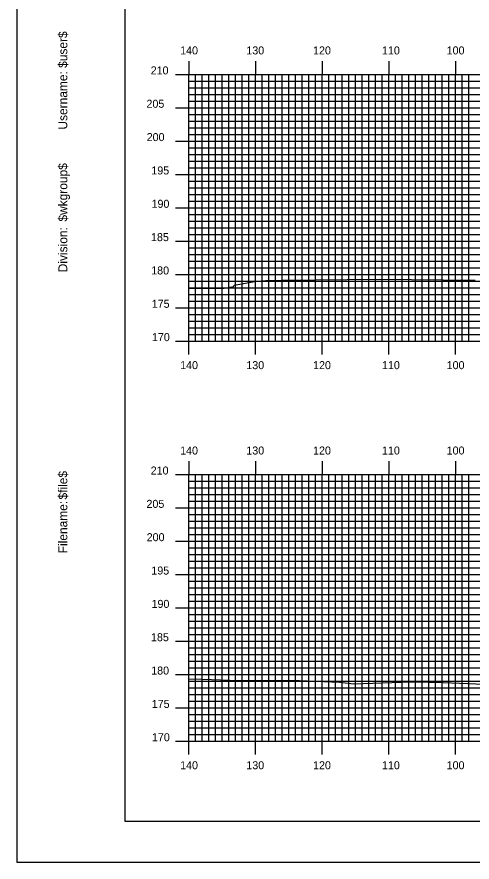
# Model space of a CAD drawing. Extents: x 1809406 to 1809749, y 442591 to 442811.
# Drawn here: x 1809406.1 to 1809474.3, y 442590.5 to 442717.3 of the extents above; entities that cross this region are included whole.
import ezdxf

# ---------------------------------------------------------------- set-up
doc = ezdxf.new("R2010")
doc.units = 0
for name, color, linetype in [('BORDER', 7, 'Continuous'), ('H_V ANNOTATION', 7, 'Continuous'), ('MAJOR', 7, 'Continuous'), ('MINOR', 7, 'Continuous'), ('PLOT BOUNDARY', 7, 'Continuous'), ('S_Roadway_Centerline', 7, 'Continuous')]:
    doc.layers.add(name, color=color, linetype=linetype)

msp = doc.modelspace()

# ---------------------------------------------------------------- linework, layer by layer
at = {"layer": 'BORDER'}
msp.add_lwpolyline([(1809422.24, 442596.67), (1809742.24, 442596.67), (1809742.24, 442806.67), (1809422.24, 442806.67)], close=True, dxfattribs=at)
at = {"layer": 'MAJOR'}
for p, q in [((1809431.84, 442710.67), (1809431.84, 442708.67)), ((1809441.84, 442710.67), (1809441.84, 442708.67)), ((1809451.84, 442710.67), (1809451.84, 442708.67)), ((1809461.84, 442710.67), (1809461.84, 442708.67)), ((1809471.84, 442710.67), (1809471.84, 442708.67)), ((1809429.83, 442708.67), (1809431.84, 442708.67)), ((1809431.84, 442708.67), (1809711.84, 442708.67)), ((1809431.84, 442668.67), (1809431.84, 442708.67)), ((1809431.84, 442668.67), (1809431.84, 442708.67)), ((1809431.84, 442708.67), (1809711.84, 442708.67)), ((1809441.84, 442668.67), (1809441.84, 442708.67)), ((1809451.84, 442668.67), (1809451.84, 442708.67)), ((1809461.84, 442668.67), (1809461.84, 442708.67)), ((1809471.84, 442668.67), (1809471.84, 442708.67)), ((1809429.83, 442703.67), (1809431.84, 442703.67)), ((1809431.84, 442703.67), (1809711.84, 442703.67)), ((1809429.83, 442698.67), (1809431.84, 442698.67)), ((1809431.84, 442698.67), (1809711.84, 442698.67)), ((1809429.83, 442693.67), (1809431.84, 442693.67)), ((1809431.84, 442693.67), (1809711.84, 442693.67)), ((1809429.83, 442688.67), (1809431.84, 442688.67)), ((1809431.84, 442688.67), (1809711.84, 442688.67)), ((1809429.83, 442683.67), (1809431.84, 442683.67)), ((1809431.84, 442683.67), (1809711.84, 442683.67)), ((1809429.83, 442678.67), (1809431.84, 442678.67)), ((1809431.84, 442678.67), (1809711.84, 442678.67)), ((1809429.83, 442673.67), (1809431.84, 442673.67)), ((1809431.84, 442673.67), (1809711.84, 442673.67)), ((1809429.83, 442668.67), (1809431.84, 442668.67)), ((1809431.84, 442668.67), (1809711.84, 442668.67)), ((1809431.84, 442668.67), (1809711.84, 442668.67)), ((1809431.84, 442666.66), (1809431.84, 442668.67)), ((1809441.84, 442666.66), (1809441.84, 442668.67)), ((1809451.84, 442666.66), (1809451.84, 442668.67)), ((1809461.84, 442666.66), (1809461.84, 442668.67)), ((1809471.84, 442666.66), (1809471.84, 442668.67)), ((1809431.84, 442650.67), (1809431.84, 442648.67)), ((1809441.84, 442650.67), (1809441.84, 442648.67)), ((1809451.84, 442650.67), (1809451.84, 442648.67)), ((1809461.84, 442650.67), (1809461.84, 442648.67)), ((1809471.84, 442650.67), (1809471.84, 442648.67)), ((1809429.83, 442648.67), (1809431.84, 442648.67)), ((1809431.84, 442648.67), (1809711.84, 442648.67)), ((1809431.84, 442608.67), (1809431.84, 442648.67)), ((1809431.84, 442608.67), (1809431.84, 442648.67)), ((1809431.84, 442648.67), (1809711.84, 442648.67)), ((1809441.84, 442608.67), (1809441.84, 442648.67)), ((1809451.84, 442608.67), (1809451.84, 442648.67)), ((1809461.84, 442608.67), (1809461.84, 442648.67)), ((1809471.84, 442608.67), (1809471.84, 442648.67)), ((1809429.83, 442643.67), (1809431.84, 442643.67)), ((1809431.84, 442643.67), (1809711.84, 442643.67)), ((1809429.83, 442638.67), (1809431.84, 442638.67)), ((1809431.84, 442638.67), (1809711.84, 442638.67)), ((1809429.83, 442633.67), (1809431.84, 442633.67)), ((1809431.84, 442633.67), (1809711.84, 442633.67)), ((1809429.83, 442628.67), (1809431.84, 442628.67)), ((1809431.84, 442628.67), (1809711.84, 442628.67)), ((1809429.83, 442623.67), (1809431.84, 442623.67)), ((1809431.84, 442623.67), (1809711.84, 442623.67)), ((1809429.83, 442618.67), (1809431.84, 442618.67)), ((1809431.84, 442618.67), (1809711.84, 442618.67)), ((1809429.83, 442613.67), (1809431.84, 442613.67)), ((1809431.84, 442613.67), (1809711.84, 442613.67)), ((1809429.83, 442608.67), (1809431.84, 442608.67)), ((1809431.84, 442608.67), (1809711.84, 442608.67)), ((1809431.84, 442608.67), (1809711.84, 442608.67)), ((1809431.84, 442606.66), (1809431.84, 442608.67)), ((1809441.84, 442606.66), (1809441.84, 442608.67)), ((1809451.84, 442606.66), (1809451.84, 442608.67)), ((1809461.84, 442606.66), (1809461.84, 442608.67)), ((1809471.84, 442606.66), (1809471.84, 442608.67))]:
    msp.add_line(p, q, dxfattribs=at)
at = {"layer": 'MINOR'}
for p, q in [((1809432.84, 442668.67), (1809432.84, 442708.67)), ((1809433.84, 442668.67), (1809433.84, 442708.67)), ((1809434.84, 442668.67), (1809434.84, 442708.67)), ((1809435.84, 442668.67), (1809435.84, 442708.67)), ((1809436.84, 442668.67), (1809436.84, 442708.67)), ((1809437.84, 442668.67), (1809437.84, 442708.67)), ((1809438.84, 442668.67), (1809438.84, 442708.67)), ((1809439.84, 442668.67), (1809439.84, 442708.67)), ((1809440.84, 442668.67), (1809440.84, 442708.67)), ((1809442.84, 442668.67), (1809442.84, 442708.67)), ((1809443.84, 442668.67), (1809443.84, 442708.67)), ((1809444.84, 442668.67), (1809444.84, 442708.67)), ((1809445.84, 442668.67), (1809445.84, 442708.67)), ((1809446.84, 442668.67), (1809446.84, 442708.67)), ((1809447.84, 442668.67), (1809447.84, 442708.67)), ((1809448.84, 442668.67), (1809448.84, 442708.67)), ((1809449.84, 442668.67), (1809449.84, 442708.67)), ((1809450.84, 442668.67), (1809450.84, 442708.67)), ((1809452.84, 442668.67), (1809452.84, 442708.67)), ((1809453.84, 442668.67), (1809453.84, 442708.67)), ((1809454.84, 442668.67), (1809454.84, 442708.67)), ((1809455.84, 442668.67), (1809455.84, 442708.67)), ((1809456.84, 442668.67), (1809456.84, 442708.67)), ((1809457.84, 442668.67), (1809457.84, 442708.67)), ((1809458.84, 442668.67), (1809458.84, 442708.67)), ((1809459.84, 442668.67), (1809459.84, 442708.67)), ((1809460.84, 442668.67), (1809460.84, 442708.67)), ((1809462.84, 442668.67), (1809462.84, 442708.67)), ((1809463.84, 442668.67), (1809463.84, 442708.67)), ((1809464.84, 442668.67), (1809464.84, 442708.67)), ((1809465.84, 442668.67), (1809465.84, 442708.67)), ((1809466.84, 442668.67), (1809466.84, 442708.67)), ((1809467.84, 442668.67), (1809467.84, 442708.67)), ((1809468.84, 442668.67), (1809468.84, 442708.67)), ((1809469.84, 442668.67), (1809469.84, 442708.67)), ((1809470.84, 442668.67), (1809470.84, 442708.67)), ((1809472.84, 442668.67), (1809472.84, 442708.67)), ((1809473.84, 442668.67), (1809473.84, 442708.67)), ((1809431.84, 442707.67), (1809711.84, 442707.67)), ((1809431.84, 442707.67), (1809433.84, 442707.67)), ((1809431.84, 442706.67), (1809711.84, 442706.67)), ((1809431.84, 442706.67), (1809433.84, 442706.67)), ((1809431.84, 442705.67), (1809711.84, 442705.67)), ((1809431.84, 442705.67), (1809433.84, 442705.67)), ((1809431.84, 442704.67), (1809711.84, 442704.67)), ((1809431.84, 442704.67), (1809433.84, 442704.67)), ((1809431.84, 442702.67), (1809711.84, 442702.67)), ((1809431.84, 442702.67), (1809433.84, 442702.67)), ((1809431.84, 442701.67), (1809711.84, 442701.67)), ((1809431.84, 442701.67), (1809433.84, 442701.67)), ((1809431.84, 442700.67), (1809711.84, 442700.67)), ((1809431.84, 442700.67), (1809433.84, 442700.67)), ((1809431.84, 442699.67), (1809711.84, 442699.67)), ((1809431.84, 442699.67), (1809433.84, 442699.67)), ((1809431.84, 442697.67), (1809711.84, 442697.67)), ((1809431.84, 442697.67), (1809433.84, 442697.67)), ((1809431.84, 442696.67), (1809711.84, 442696.67)), ((1809431.84, 442696.67), (1809433.84, 442696.67)), ((1809431.84, 442695.67), (1809711.84, 442695.67)), ((1809431.84, 442695.67), (1809433.84, 442695.67)), ((1809431.84, 442694.67), (1809711.84, 442694.67)), ((1809431.84, 442694.67), (1809433.84, 442694.67)), ((1809431.84, 442692.67), (1809711.84, 442692.67)), ((1809431.84, 442692.67), (1809433.84, 442692.67)), ((1809431.84, 442691.67), (1809711.84, 442691.67)), ((1809431.84, 442691.67), (1809433.84, 442691.67)), ((1809431.84, 442690.67), (1809711.84, 442690.67)), ((1809431.84, 442690.67), (1809433.84, 442690.67)), ((1809431.84, 442689.67), (1809711.84, 442689.67)), ((1809431.84, 442689.67), (1809433.84, 442689.67)), ((1809431.84, 442687.67), (1809711.84, 442687.67)), ((1809431.84, 442687.67), (1809433.84, 442687.67)), ((1809431.84, 442686.67), (1809711.84, 442686.67)), ((1809431.84, 442686.67), (1809433.84, 442686.67)), ((1809431.84, 442685.67), (1809711.84, 442685.67)), ((1809431.84, 442685.67), (1809433.84, 442685.67)), ((1809431.84, 442684.67), (1809711.84, 442684.67)), ((1809431.84, 442684.67), (1809433.84, 442684.67)), ((1809431.84, 442682.67), (1809711.84, 442682.67)), ((1809431.84, 442682.67), (1809433.84, 442682.67)), ((1809431.84, 442681.67), (1809711.84, 442681.67)), ((1809431.84, 442681.67), (1809433.84, 442681.67)), ((1809431.84, 442680.67), (1809711.84, 442680.67)), ((1809431.84, 442680.67), (1809433.84, 442680.67)), ((1809431.84, 442679.67), (1809711.84, 442679.67)), ((1809431.84, 442679.67), (1809433.84, 442679.67)), ((1809431.84, 442677.67), (1809711.84, 442677.67)), ((1809431.84, 442677.67), (1809433.84, 442677.67)), ((1809431.84, 442676.67), (1809711.84, 442676.67)), ((1809431.84, 442676.67), (1809433.84, 442676.67)), ((1809431.84, 442675.67), (1809711.84, 442675.67)), ((1809431.84, 442675.67), (1809433.84, 442675.67)), ((1809431.84, 442674.67), (1809711.84, 442674.67)), ((1809431.84, 442674.67), (1809433.84, 442674.67)), ((1809431.84, 442672.67), (1809711.84, 442672.67)), ((1809431.84, 442672.67), (1809433.84, 442672.67)), ((1809431.84, 442671.67), (1809711.84, 442671.67)), ((1809431.84, 442671.67), (1809433.84, 442671.67)), ((1809431.84, 442670.67), (1809711.84, 442670.67)), ((1809431.84, 442670.67), (1809433.84, 442670.67)), ((1809431.84, 442669.67), (1809711.84, 442669.67)), ((1809431.84, 442669.67), (1809433.84, 442669.67)), ((1809432.84, 442608.67), (1809432.84, 442648.67)), ((1809433.84, 442608.67), (1809433.84, 442648.67)), ((1809434.84, 442608.67), (1809434.84, 442648.67)), ((1809435.84, 442608.67), (1809435.84, 442648.67)), ((1809436.84, 442608.67), (1809436.84, 442648.67)), ((1809437.84, 442608.67), (1809437.84, 442648.67)), ((1809438.84, 442608.67), (1809438.84, 442648.67)), ((1809439.84, 442608.67), (1809439.84, 442648.67)), ((1809440.84, 442608.67), (1809440.84, 442648.67)), ((1809442.84, 442608.67), (1809442.84, 442648.67)), ((1809443.84, 442608.67), (1809443.84, 442648.67)), ((1809444.84, 442608.67), (1809444.84, 442648.67)), ((1809445.84, 442608.67), (1809445.84, 442648.67)), ((1809446.84, 442608.67), (1809446.84, 442648.67)), ((1809447.84, 442608.67), (1809447.84, 442648.67)), ((1809448.84, 442608.67), (1809448.84, 442648.67)), ((1809449.84, 442608.67), (1809449.84, 442648.67)), ((1809450.84, 442608.67), (1809450.84, 442648.67)), ((1809452.84, 442608.67), (1809452.84, 442648.67)), ((1809453.84, 442608.67), (1809453.84, 442648.67)), ((1809454.84, 442608.67), (1809454.84, 442648.67)), ((1809455.84, 442608.67), (1809455.84, 442648.67)), ((1809456.84, 442608.67), (1809456.84, 442648.67)), ((1809457.84, 442608.67), (1809457.84, 442648.67)), ((1809458.84, 442608.67), (1809458.84, 442648.67)), ((1809459.84, 442608.67), (1809459.84, 442648.67)), ((1809460.84, 442608.67), (1809460.84, 442648.67)), ((1809462.84, 442608.67), (1809462.84, 442648.67)), ((1809463.84, 442608.67), (1809463.84, 442648.67)), ((1809464.84, 442608.67), (1809464.84, 442648.67)), ((1809465.84, 442608.67), (1809465.84, 442648.67)), ((1809466.84, 442608.67), (1809466.84, 442648.67)), ((1809467.84, 442608.67), (1809467.84, 442648.67)), ((1809468.84, 442608.67), (1809468.84, 442648.67)), ((1809469.84, 442608.67), (1809469.84, 442648.67)), ((1809470.84, 442608.67), (1809470.84, 442648.67)), ((1809472.84, 442608.67), (1809472.84, 442648.67)), ((1809473.84, 442608.67), (1809473.84, 442648.67)), ((1809431.84, 442647.67), (1809711.84, 442647.67)), ((1809431.84, 442647.67), (1809433.84, 442647.67)), ((1809431.84, 442646.67), (1809711.84, 442646.67)), ((1809431.84, 442646.67), (1809433.84, 442646.67)), ((1809431.84, 442645.67), (1809711.84, 442645.67)), ((1809431.84, 442645.67), (1809433.84, 442645.67)), ((1809431.84, 442644.67), (1809711.84, 442644.67)), ((1809431.84, 442644.67), (1809433.84, 442644.67)), ((1809431.84, 442642.67), (1809711.84, 442642.67)), ((1809431.84, 442642.67), (1809433.84, 442642.67)), ((1809431.84, 442641.67), (1809711.84, 442641.67)), ((1809431.84, 442641.67), (1809433.84, 442641.67)), ((1809431.84, 442640.67), (1809711.84, 442640.67)), ((1809431.84, 442640.67), (1809433.84, 442640.67)), ((1809431.84, 442639.67), (1809711.84, 442639.67)), ((1809431.84, 442639.67), (1809433.84, 442639.67)), ((1809431.84, 442637.67), (1809711.84, 442637.67)), ((1809431.84, 442637.67), (1809433.84, 442637.67)), ((1809431.84, 442636.67), (1809711.84, 442636.67)), ((1809431.84, 442636.67), (1809433.84, 442636.67)), ((1809431.84, 442635.67), (1809711.84, 442635.67)), ((1809431.84, 442635.67), (1809433.84, 442635.67)), ((1809431.84, 442634.67), (1809711.84, 442634.67)), ((1809431.84, 442634.67), (1809433.84, 442634.67)), ((1809431.84, 442632.67), (1809711.84, 442632.67)), ((1809431.84, 442632.67), (1809433.84, 442632.67)), ((1809431.84, 442631.67), (1809711.84, 442631.67)), ((1809431.84, 442631.67), (1809433.84, 442631.67)), ((1809431.84, 442630.67), (1809711.84, 442630.67)), ((1809431.84, 442630.67), (1809433.84, 442630.67)), ((1809431.84, 442629.67), (1809711.84, 442629.67)), ((1809431.84, 442629.67), (1809433.84, 442629.67)), ((1809431.84, 442627.67), (1809711.84, 442627.67)), ((1809431.84, 442627.67), (1809433.84, 442627.67)), ((1809431.84, 442626.67), (1809711.84, 442626.67)), ((1809431.84, 442626.67), (1809433.84, 442626.67)), ((1809431.84, 442625.67), (1809711.84, 442625.67)), ((1809431.84, 442625.67), (1809433.84, 442625.67)), ((1809431.84, 442624.67), (1809711.84, 442624.67)), ((1809431.84, 442624.67), (1809433.84, 442624.67)), ((1809431.84, 442622.67), (1809711.84, 442622.67)), ((1809431.84, 442622.67), (1809433.84, 442622.67)), ((1809431.84, 442621.67), (1809711.84, 442621.67)), ((1809431.84, 442621.67), (1809433.84, 442621.67)), ((1809431.84, 442620.67), (1809711.84, 442620.67)), ((1809431.84, 442620.67), (1809433.84, 442620.67)), ((1809431.84, 442619.67), (1809711.84, 442619.67)), ((1809431.84, 442619.67), (1809433.84, 442619.67)), ((1809431.84, 442617.67), (1809711.84, 442617.67)), ((1809431.84, 442617.67), (1809433.84, 442617.67)), ((1809431.84, 442616.67), (1809711.84, 442616.67)), ((1809431.84, 442616.67), (1809433.84, 442616.67)), ((1809431.84, 442615.67), (1809711.84, 442615.67)), ((1809431.84, 442615.67), (1809433.84, 442615.67)), ((1809431.84, 442614.67), (1809711.84, 442614.67)), ((1809431.84, 442614.67), (1809433.84, 442614.67)), ((1809431.84, 442612.67), (1809711.84, 442612.67)), ((1809431.84, 442612.67), (1809433.84, 442612.67)), ((1809431.84, 442611.67), (1809711.84, 442611.67)), ((1809431.84, 442611.67), (1809433.84, 442611.67)), ((1809431.84, 442610.67), (1809711.84, 442610.67)), ((1809431.84, 442610.67), (1809433.84, 442610.67)), ((1809431.84, 442609.67), (1809711.84, 442609.67)), ((1809431.84, 442609.67), (1809433.84, 442609.67))]:
    msp.add_line(p, q, dxfattribs=at)
at = {"layer": 'PLOT BOUNDARY'}
msp.add_lwpolyline([(1809406.05, 442590.55), (1809746.05, 442590.55), (1809746.05, 442810.55), (1809406.05, 442810.55)], close=True, dxfattribs=at)
at = {"layer": 'S_Roadway_Centerline'}
for points in [[(1809431.84, 442676.6), (1809436.75, 442676.6), (1809436.9, 442676.58), (1809438.55, 442676.85), (1809438.64, 442677.07), (1809441.97, 442677.67), (1809443.41, 442677.79), (1809445.91, 442677.8), (1809460.46, 442677.97), (1809474.81, 442677.8)], [(1809431.84, 442618.04), (1809433.87, 442617.99), (1809437.96, 442617.83), (1809441.14, 442617.8), (1809448.42, 442617.78), (1809454.43, 442617.54), (1809456.61, 442617.26), (1809465.13, 442617.57), (1809467.73, 442617.51), (1809468.81, 442617.51), (1809474.91, 442617.3), (1809478.06, 442617.07), (1809479.02, 442616.84), (1809483.92, 442616.59), (1809487.66, 442616.59), (1809488.59, 442616.59), (1809502.91, 442616.65), (1809506.56, 442616.66), (1809516.95, 442616.65), (1809524.81, 442616.64), (1809531.99, 442616.66), (1809543.3, 442616.68)]]:
    msp.add_lwpolyline(points, dxfattribs=at)

# ---------------------------------------------------------------- texts
at = {"layer": 'BORDER'}
for s, p in [('$user$', (1809413.61, 442709.65)), ('Username:', (1809413.61, 442700.4)), ('$wkgroup$', (1809413.61, 442686.6)), ('Division:', (1809413.61, 442679)), ('$file$', (1809413.61, 442644.92)), ('Filename:', (1809413.61, 442636.86))]:
    msp.add_text(s, height=1.339, rotation=90, dxfattribs=at).set_placement(p)
at = {"layer": 'H_V ANNOTATION'}
for s, p in [('140', (1809430.54, 442711.67)), ('130', (1809440.47, 442711.67)), ('120', (1809450.48, 442711.67)), ('110', (1809460.82, 442711.67)), ('100', (1809470.52, 442711.67)), ('210', (1809426.12, 442708.67)), ('205', (1809425.49, 442703.67)), ('200', (1809425.52, 442698.67)), ('195', (1809426.22, 442693.67)), ('190', (1809426.25, 442688.67)), ('185', (1809426.17, 442683.67)), ('180', (1809426.2, 442678.67)), ('175', (1809426.28, 442673.67)), ('170', (1809426.31, 442668.67)), ('140', (1809430.54, 442664.47)), ('130', (1809440.47, 442664.47)), ('120', (1809450.48, 442664.47)), ('110', (1809460.82, 442664.47)), ('100', (1809470.52, 442664.47)), ('140', (1809430.54, 442651.67)), ('130', (1809440.47, 442651.67)), ('120', (1809450.48, 442651.67)), ('110', (1809460.82, 442651.67)), ('100', (1809470.52, 442651.67)), ('210', (1809426.12, 442648.67)), ('205', (1809425.49, 442643.67)), ('200', (1809425.52, 442638.67)), ('195', (1809426.22, 442633.67)), ('190', (1809426.25, 442628.67)), ('185', (1809426.17, 442623.67)), ('180', (1809426.2, 442618.67)), ('175', (1809426.28, 442613.67)), ('170', (1809426.31, 442608.67)), ('140', (1809430.54, 442604.47)), ('130', (1809440.47, 442604.47)), ('120', (1809450.48, 442604.47)), ('110', (1809460.82, 442604.47)), ('100', (1809470.52, 442604.47))]:
    msp.add_text(s, height=1.2, dxfattribs=at).set_placement(p)
at = {"layer": 'MAJOR'}
for p in [(1809431.83, 442668.67), (1809431.83, 442608.67)]:
    msp.add_text('-', height=0.012, dxfattribs=at).set_placement(p)

doc.saveas('drawing.dxf')
